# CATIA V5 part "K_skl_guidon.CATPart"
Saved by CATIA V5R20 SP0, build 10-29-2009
Part number: skl_guidon
Publications: "Point.3", "axe_guidon_avant", "axe_guidon_bati", "Plan_guidon_bati", "Point.1", "Point.2", "Plan_ref"
Bounding box of the stored display mesh (mm): x -20 to 20, y 0 to 0, z 0 to 370
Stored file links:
  G:\Khaled_CFAO_2011\SIL\SIL_GR2\ahabrial\ahabrial\Khaled\CAD_ThinkMOTION\K_skl_guidon.CATPart
  G:\Données\Ecole\IFMA\2A\Thinkmotion2\Etape18\trotinette.CATProduct
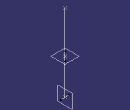
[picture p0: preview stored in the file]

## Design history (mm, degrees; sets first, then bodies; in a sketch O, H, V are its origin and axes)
External parameters (linked from other documents)
  External.hauteur_bati = 170 mm
Set1
  Point1: linked copy from another document
  Point2: linked copy from another document
  Plane1 "Plan_ref": linked copy from another document
Body1 (main body)
  Line1 "Droite_guidon": type PtPt, FirstPoint Point1, SecondPoint Point2
  Point3 "Point.3_guidon_bati": type OnCurve, Support Line1, Length 170 {= External.hauteur_bati}
  Line2 "axe_guidon_avant": type Normal, RefPoint Point2, RefSkin Plane1, Start -20, End 20
  Line3 "axe_guidon_bati": type PtDir, RefPoint Point3, Direction Line1, Start -20, End 20
  Plane2 "Plan_guidon_bati": type Normal, Curve Line3, RefPoint Point3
